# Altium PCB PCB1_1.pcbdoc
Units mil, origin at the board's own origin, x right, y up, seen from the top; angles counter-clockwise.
Board outline 2362.2 x 3149.61 mil, 4 copper layers (Top Layer, Inner1, Inner2, Bottom Layer), stack 62.447 mil thick; 35 components, 41 nets, 160 pads, 134 vias.
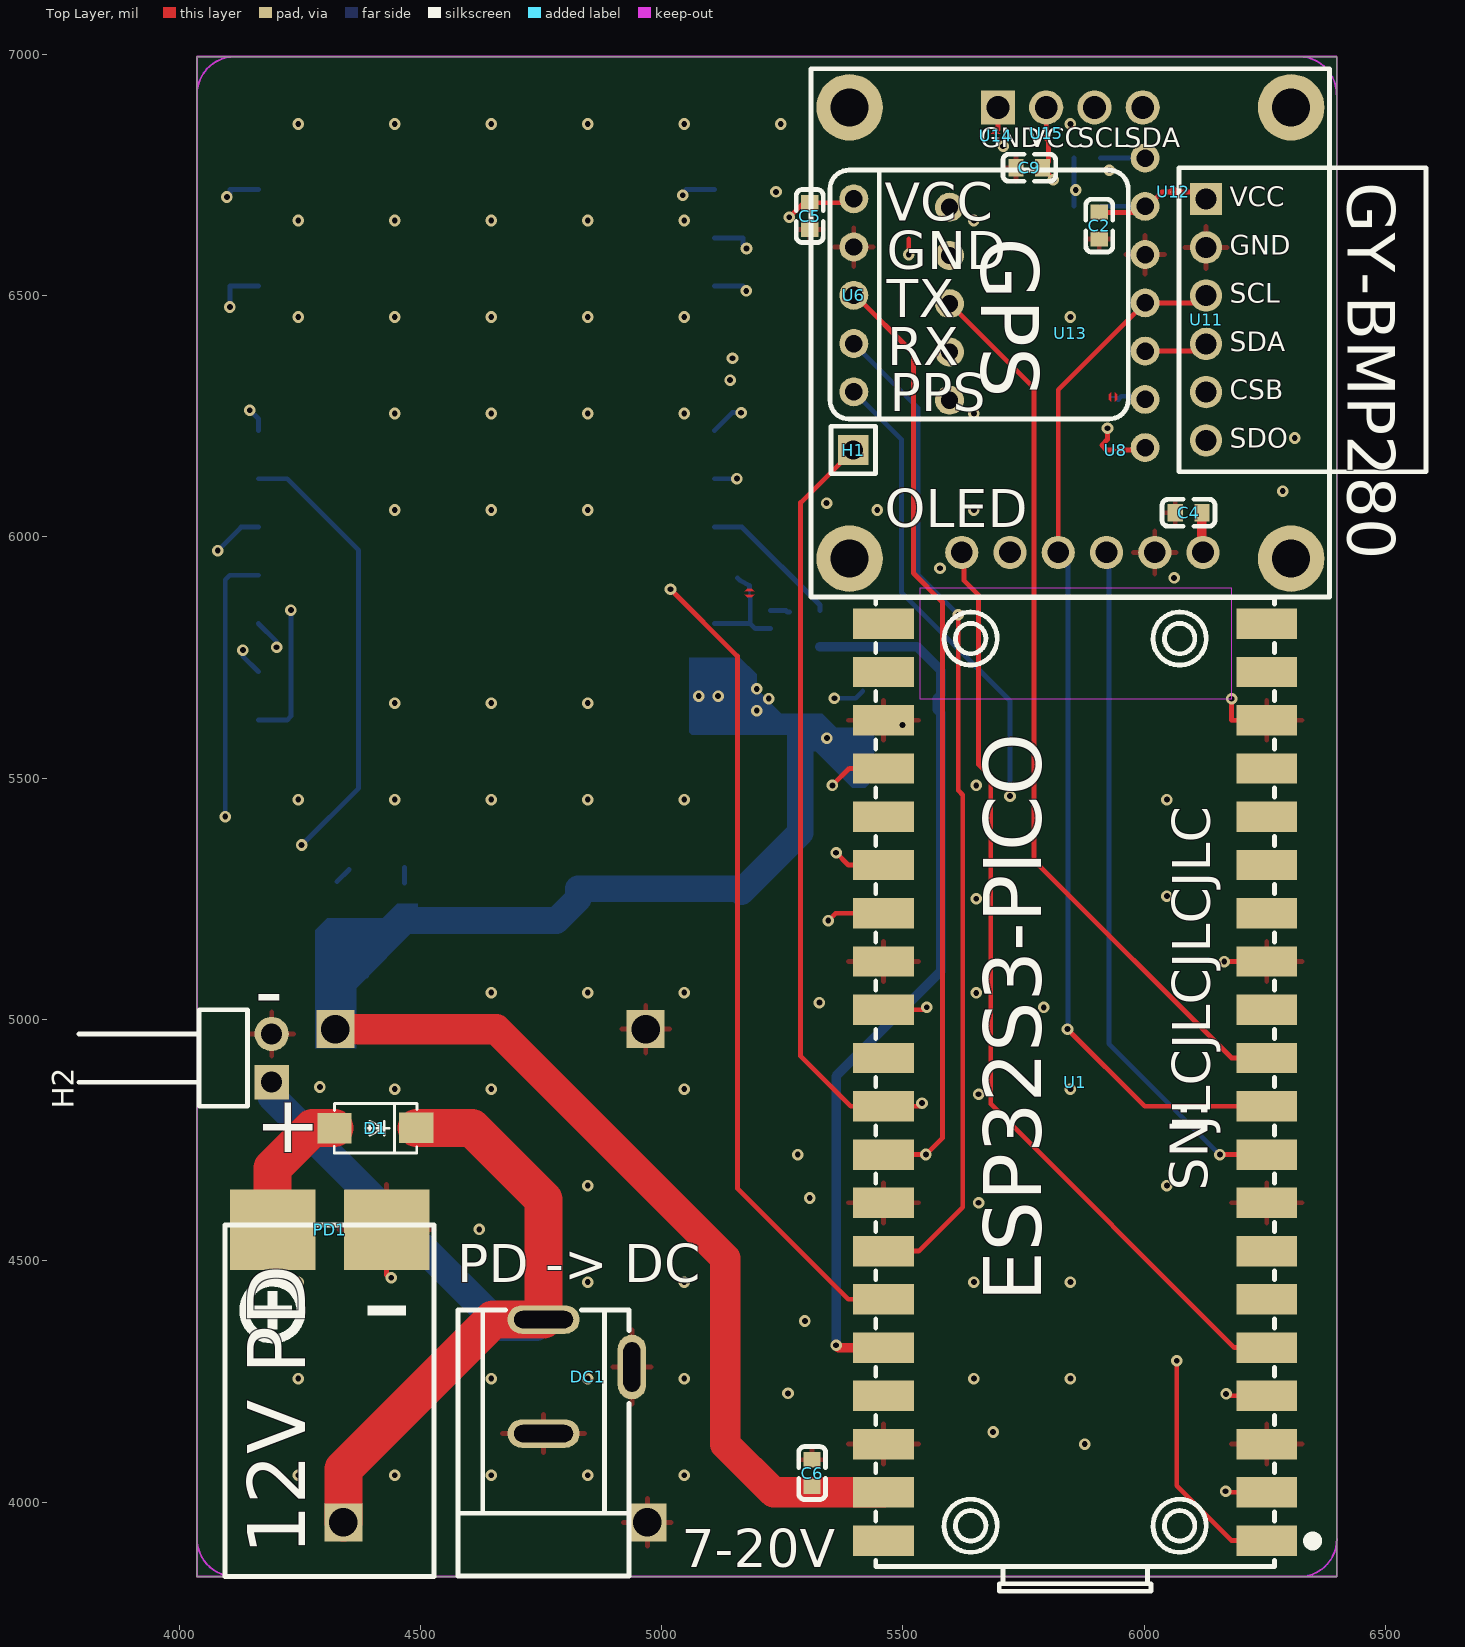
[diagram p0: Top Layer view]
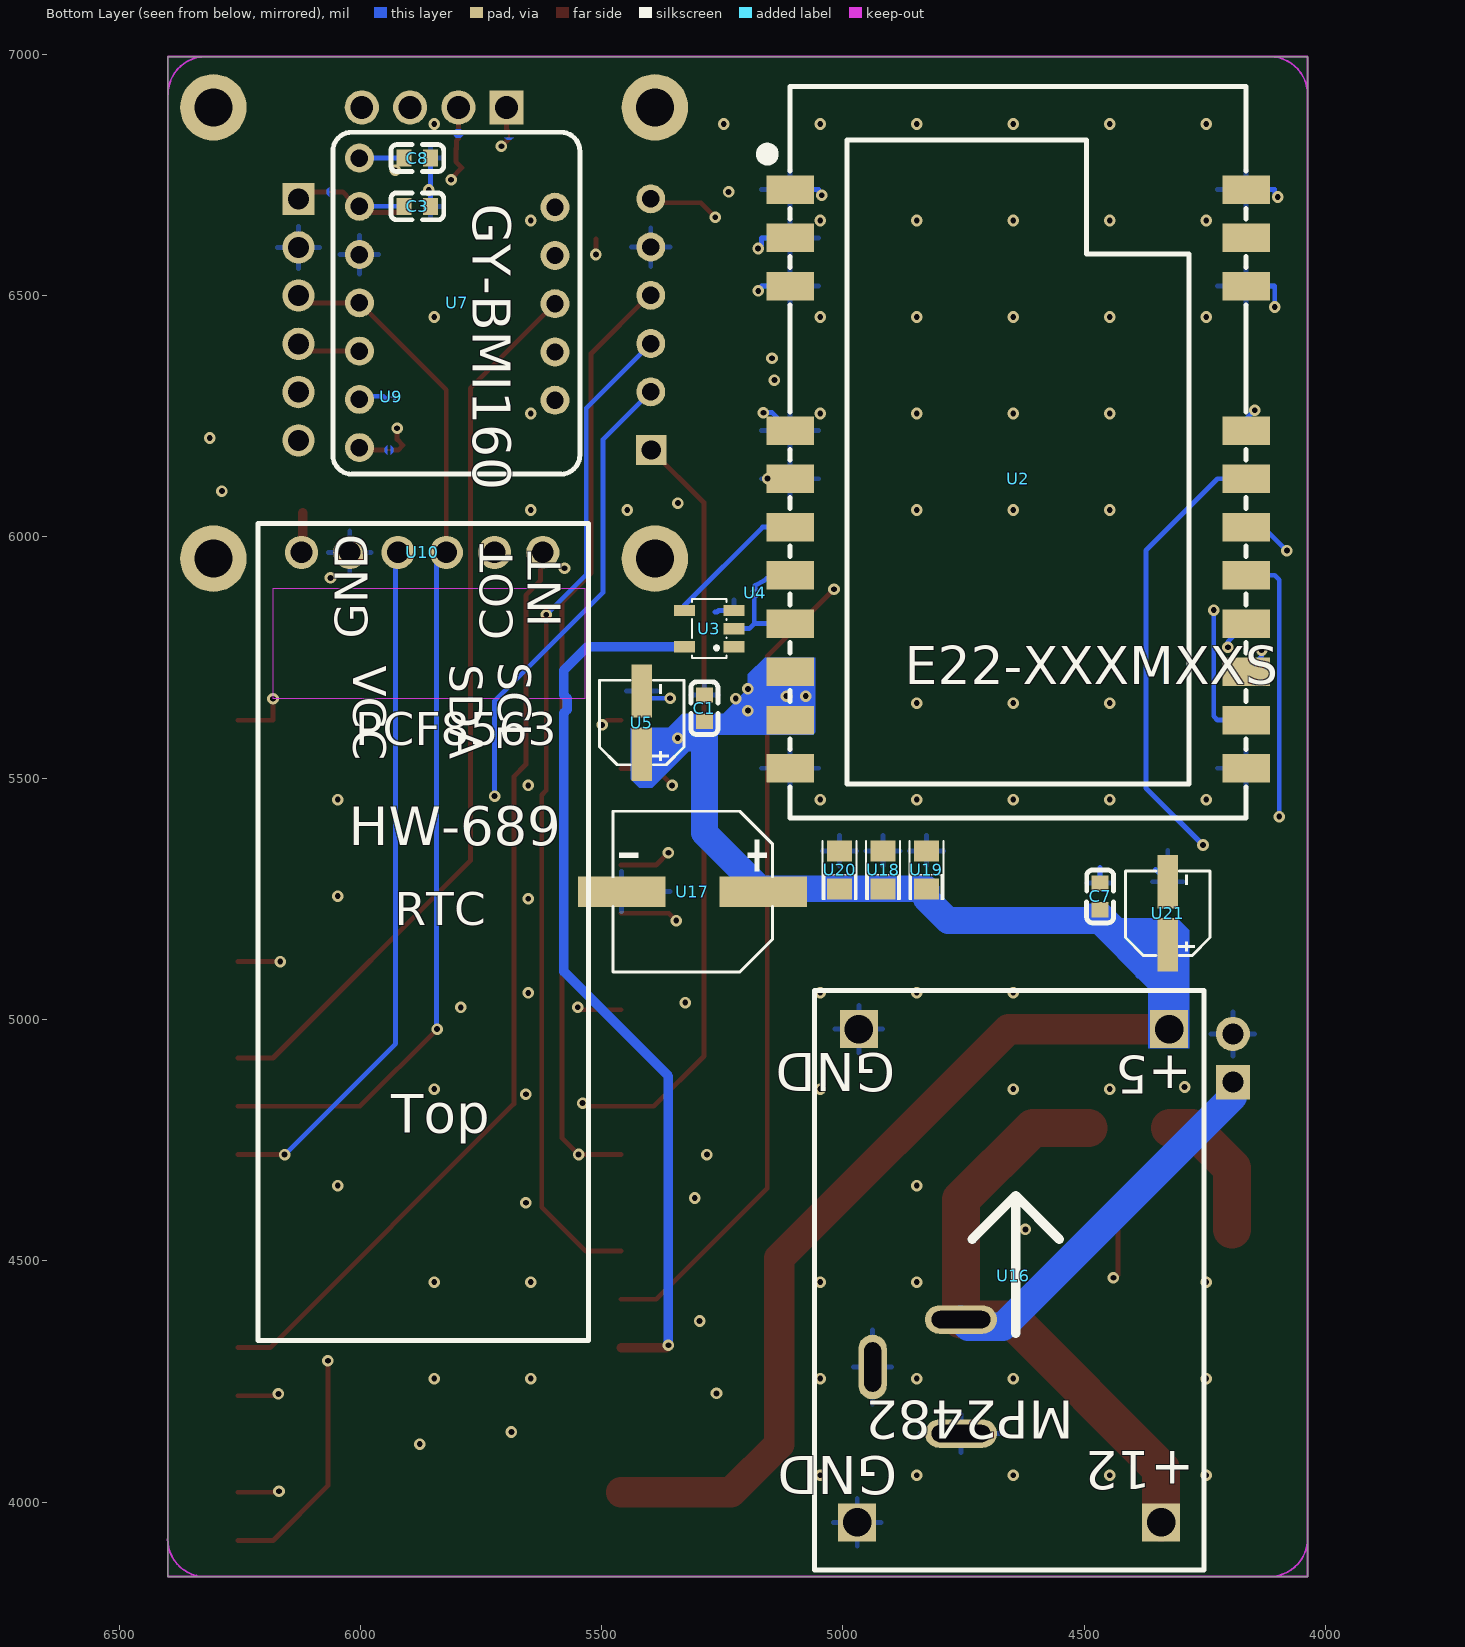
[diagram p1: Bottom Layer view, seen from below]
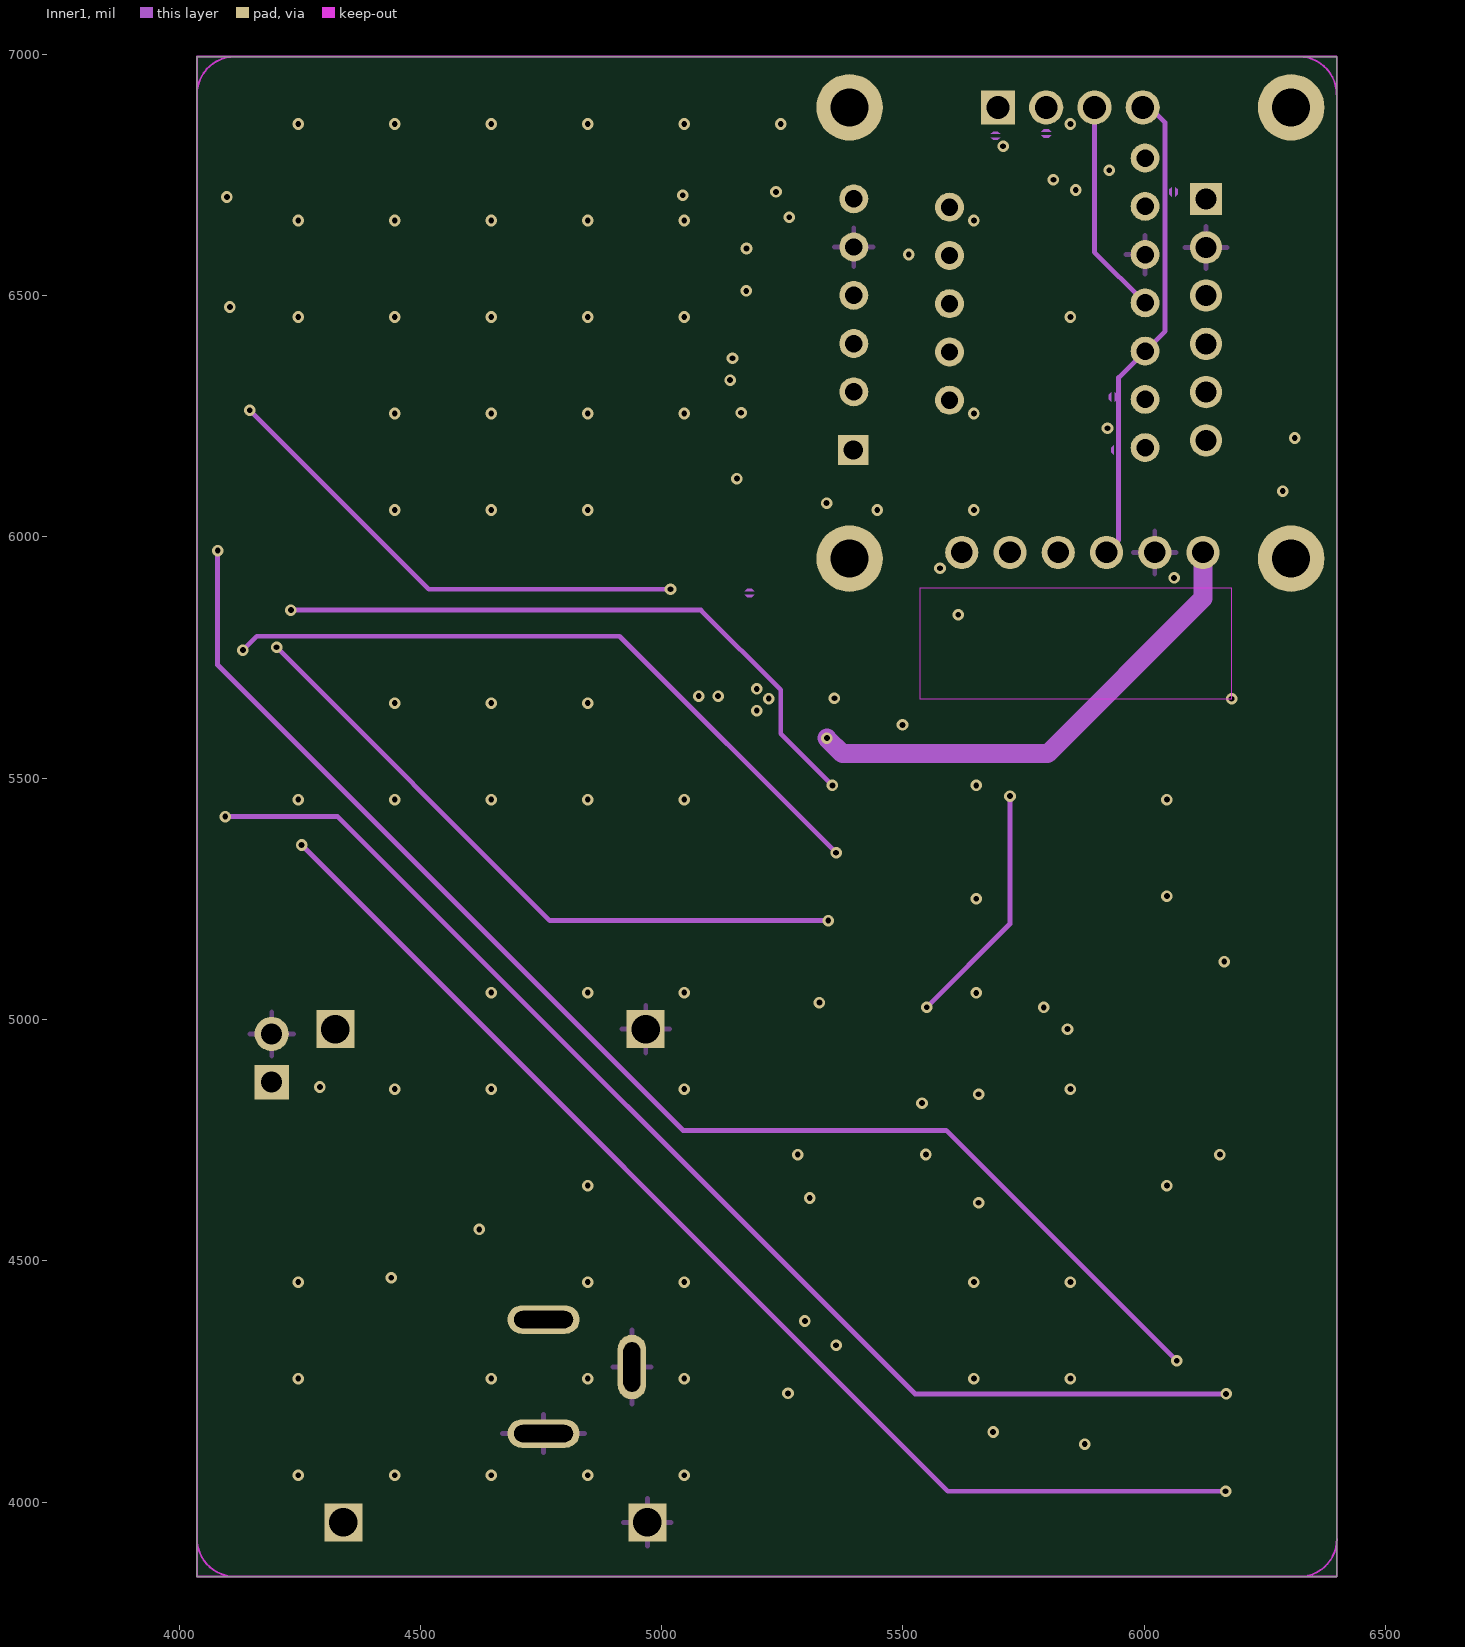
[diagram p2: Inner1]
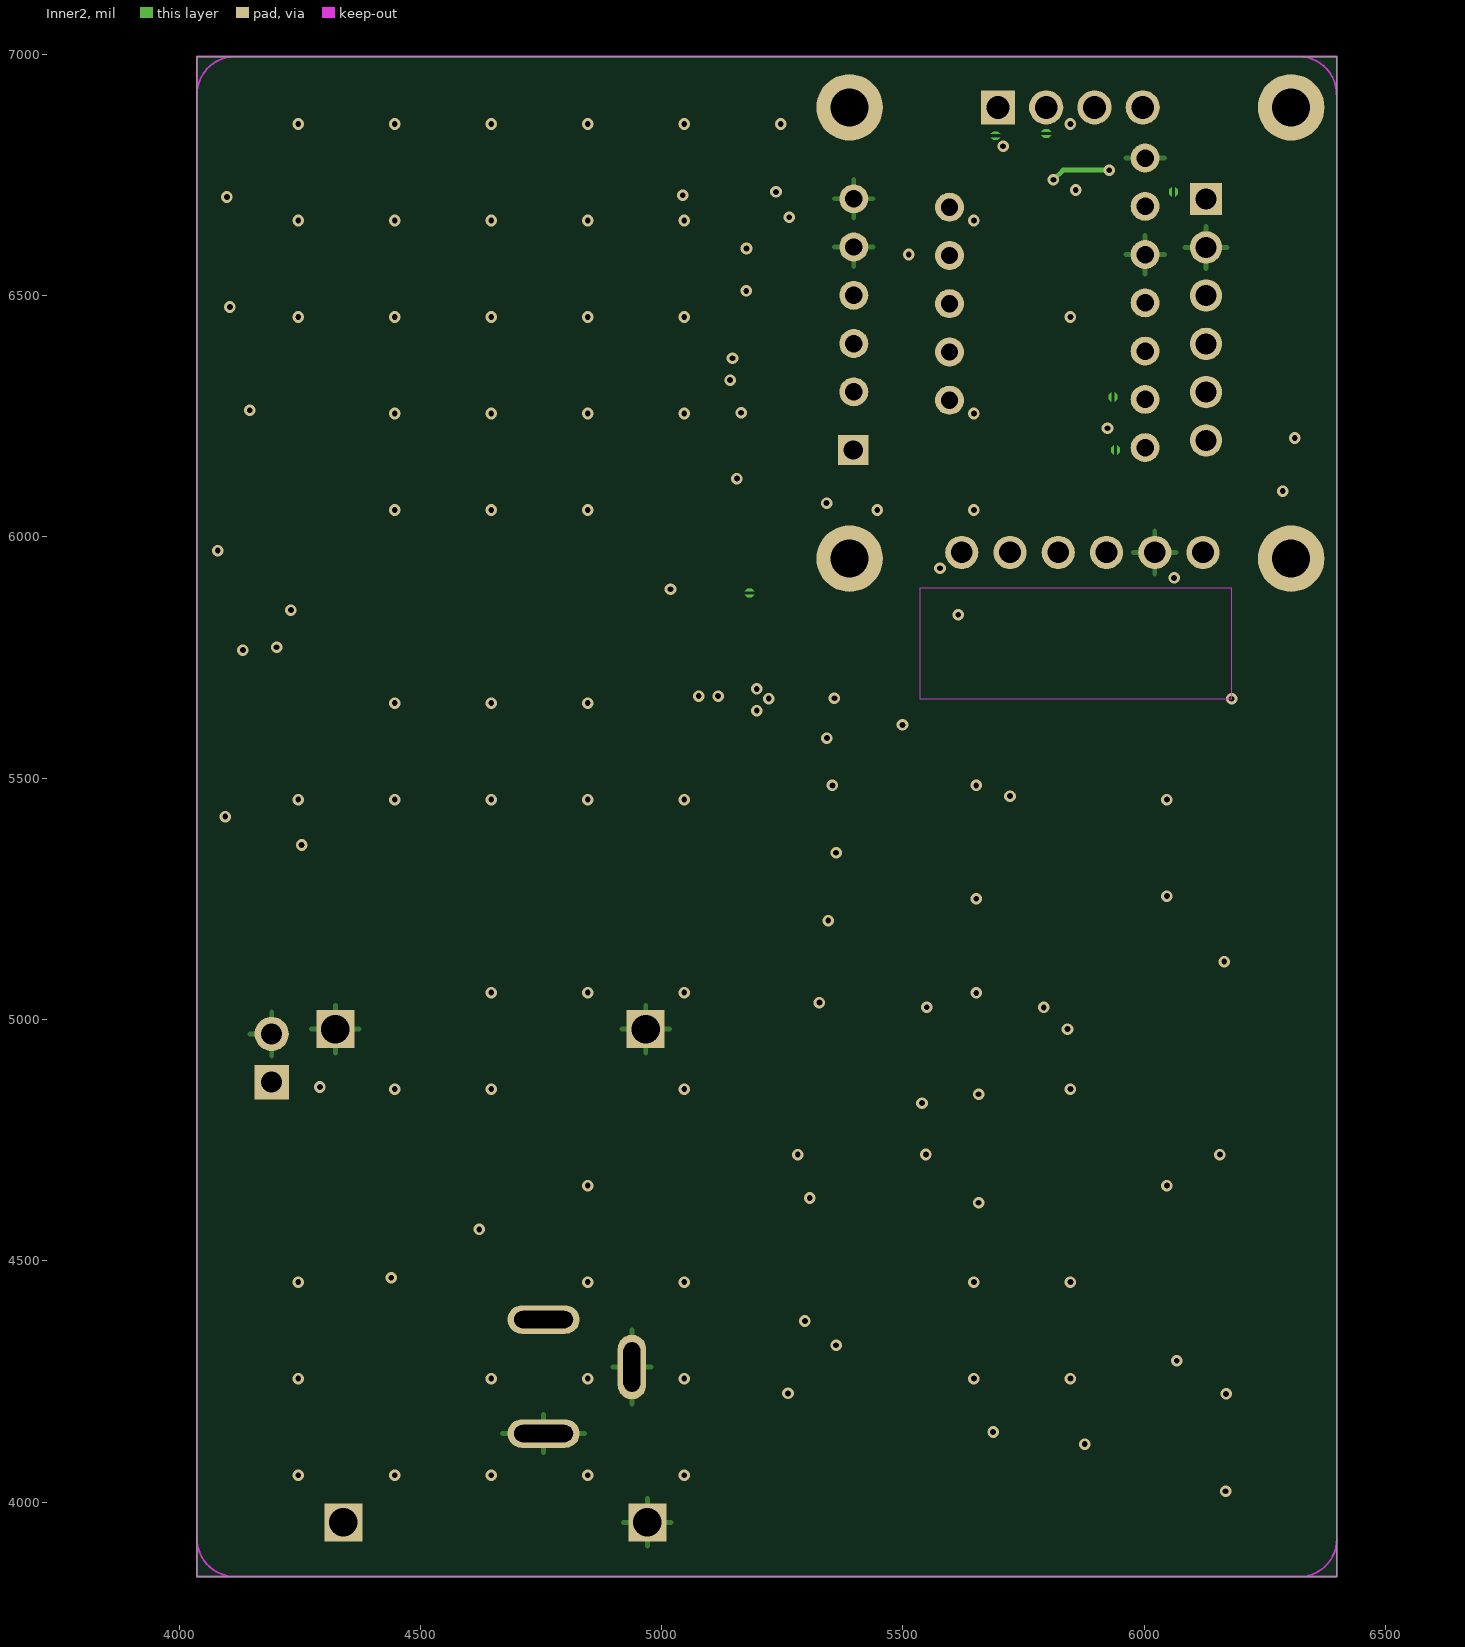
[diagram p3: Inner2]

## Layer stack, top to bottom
Top Layer: signal copper 1.378
Dielectric1: surface 8.283, 7628 RC49% 8.6mil, Dk 0
Inner1: signal copper 0.598
Dielectric2: surface 41.929, 1.1mm H/HOZ Copper, Dk 0
Inner2: signal copper 0.598
Dielectric3: surface 8.283, 7628 RC49% 8.6mil, Dk 0
Bottom Layer: signal copper 1.378

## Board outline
4036.85,6995.16 4036.85,3845.55 6399.06,3845.55 6399.06,6995.16

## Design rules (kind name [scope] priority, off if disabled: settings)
BoardOutlineClearance copperThickness1oz [All] p0: genericclearance=10 ignorepadtopadclearanceinfootprint=FALSE except(0: Arc-SplitContinuation Track-SplitContinuation SMDPad-SplitContinuation THPad-SplitContinuation Via-SplitContinuation Fill-SplitContinuation Poly-SplitContinuation Region-SplitContinuation Text-SplitContinuation)
BoardOutlineClearance copperThickness2oz [All] p0: genericclearance=10 ignorepadtopadclearanceinfootprint=FALSE except(0: Arc-SplitContinuation Track-SplitContinuation SMDPad-SplitContinuation THPad-SplitContinuation Via-SplitContinuation Fill-SplitContinuation Poly-SplitContinuation Region-SplitContinuation Text-SplitContinuation)
BoardOutlineClearance otherClearance [All] p0: genericclearance=10 ignorepadtopadclearanceinfootprint=FALSE except(0: Arc-SplitContinuation Track-SplitContinuation SMDPad-SplitContinuation THPad-SplitContinuation Via-SplitContinuation Fill-SplitContinuation Poly-SplitContinuation Region-SplitContinuation Text-SplitContinuation)
Clearance copperThickness1oz [All] p1: gap=7 ignorepadtopadclearanceinfootprint=FALSE
Clearance copperThickness2oz [All] p1: gap=7 ignorepadtopadclearanceinfootprint=FALSE
Clearance otherClearance [All] p1: gap=7 ignorepadtopadclearanceinfootprint=FALSE
DiffPairsRouting differentialPair [All] p1: maxuncoupledlength=10 minlimit=6 maxlimit=Infinity mostfreqgap=6 toplayer_minwidth=5 toplayer_prefwidth=10 toplayer_maxwidth=100 bottomlayer_minwidth=5 bottomlayer_prefwidth=10 bottomlayer_maxwidth=100 midlayer1_minwidth=5 midlayer1_prefwidth=10 midlayer1_maxwidth=100 midlayer2_minwidth=5 midlayer2_prefwidth=10 midlayer2_maxwidth=100
PasteMaskExpansion pasteMaskExpansion [All] p1: expansion=0
PlaneConnect innerPlane [All] p1: planeconnectstyle=Relief reliefexpansion=20 reliefentries=4 reliefconductorwidth=10 reliefairgap=10
PolygonConnect copperRegion [All] p1: connectstyle=Relief reliefentries=4 reliefconductorwidth=10 polygonreliefangle="90 Angle" airgapwidth=10
RoutingVias viaSize [All] p1: viastyle="Through Hole" holewidth=12.0078 minholewidth=11.811 maxholewidth=248.0314 width=12.0078 minwidth=11.811 maxwidth=248.0314
SolderMaskExpansion solderMaskExpansion [IsVia] p1: useseparateexpansions=TRUE expansion=-1000 expansionbottom=-1000
SolderMaskExpansion solderMaskExpansion [All] p2: useseparateexpansions=TRUE expansion=2 expansionbottom=2
Width copperThickness1oz [All] p1: maxlimit=100 minlimit=5 preferedwidth=10
Width copperThickness2oz [All] p1: maxlimit=100 minlimit=8 preferedwidth=10

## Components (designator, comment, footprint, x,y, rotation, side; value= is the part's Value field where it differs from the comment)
C1 "100nF" C0603 5286.85,5645 r270 bottom
C2 "100nF" C0603 5906.85,6645 r90 top
C3 "100nF" C0603 5881.85,6685 r0 bottom
C4 "100nF" C0603 6091.85,6050 r0 top
C5 "100nF" C0603 5306.85,6664.88 r90 top
C6 "100nF" C0603 5311.85,4060 r270 top
C7 "100nF" C0603 4466.85,5254.88 r270 bottom
C8 "100nF" C0603 5881.85,6785 r0 bottom
C9 "100nF" C0603 5761.85,6765 r0 top
D1 "SS54" SMA_L4.3-W2.6-LS5.0-FD 4406.85,4775 r0 top
DC1 "DC-005-A200" DC-IN-TH_DC-005-A200 4846.85,4260 r90 top
H1 "A254N01-0B1P51-H25A60" HDR-TH_1P-P2.54-V-M-3 5396.85,6180 r0 top
H2 "LAIL-PZ2.54-2P-W" HDR-TH_2P-P2.54-H-M-W10.0 4191.85,4920 r90 top
PD1 "" PDC004-PD诱骗模块 4311.85,4210 r180 top
U1 "ESP32-S3-Pico" LCC-40_L51.0-W21.0-P2.54-BL_RP2040-BASED 5856.85,4870 r90 top
U2 "E22-900M30S" WIRELM-SMD_E22-900M30S 4636.85,6120 r0 bottom
U3 "SN74LVC1G14DBVR" SOT-23-5_L3.0-W1.7-P0.95-LS2.8-BR 5276.85,5810 r180 bottom
U4 "" SB 5191.85,5880 r270 bottom
U5 "22uF" CAP-SMD_BD4.0-L4.3-W4.3-LS5.0-FD 5416.85,5615 r90 bottom
U6 "" ATGM336H 5651.85,6495 r270 top
U7 "" GY-BMI160 5716.85,6495 r180 bottom
U8 "" SB 5936.85,6190 r180 top
U9 "" SB 5931.85,6280 r180 bottom
U10 "PCF8563 HW-689 MODULE" PCF8563-I2C-2.54-1*6 5871.85,5175 r180 bottom
U11 "" GY-BMP280 6071.85,6765 r270 top
U12 "" SB 6056.85,6725 r180 top
U13 "" "OLED 0.96寸" 5696.85,6890 r0 top
U14 "" SB 5701.85,6835 r90 top
U15 "" SB 5806.85,6840 r90 top
U16 "" MP2482 4251.85,5060 r0 bottom
U17 "16V470UF" CAP-SMD_BD8.0-L8.3-W8.3-LS9.3-FD 5311.85,5265 r0 bottom
U18 "10uf" CAP-SMD_L2.0-W1.3-FD 4916.85,5310 r90 bottom
U19 "10uf" CAP-SMD_L2.0-W1.3-FD 4826.85,5310 r90 bottom
U20 "10uf" CAP-SMD_L2.0-W1.3-FD 5006.85,5310 r90 bottom
U21 "22uF" CAP-SMD_BD4.0-L4.3-W4.3-LS5.0-FD 4326.85,5220 r90 bottom

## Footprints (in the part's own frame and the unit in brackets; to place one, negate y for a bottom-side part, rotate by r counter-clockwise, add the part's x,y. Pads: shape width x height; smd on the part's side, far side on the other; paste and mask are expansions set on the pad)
ATGM336H [mil]
  round 60 hole 36: 1(-205.63,-253.74) 2(-105.63,-253.74) 3(-5.63,-253.74) 4(94.37,-253.74) 5(194.37,-253.74)
  silkscreen extent -265,-303 251,315
C0603 [mm]
  rect 0.8x0.9 smd: 1(-0.7,0) 2(0.7,0)
  silkscreen extent -1.39,-0.71 1.39,0.71
CAP-SMD_BD4.0-L4.3-W4.3-LS5.0-FD [mm]
  rect 2.8x1.1 smd: 1(-1.661,0) 2(1.661,0)
  silkscreen extent -2.22,-2.23 2.24,2.23
CAP-SMD_BD8.0-L8.3-W8.3-LS9.3-FD [mm]
  rect 4.6x1.6 smd: 1(-3.724,0) 2(3.724,0)
  silkscreen extent -4.23,-4.23 4.18,4.23
CAP-SMD_L2.0-W1.3-FD [mm]
  rect 1.1x1.3 smd paste+0 mask+0.05: 1(-1,0) 2(1,0)
  silkscreen extent -1.57,-0.89 1.52,0.89
DC-IN-TH_DC-005-A200 [mm]
  oval 1.5x3.8 hole 0.9 slot 3.1 at 90 deg copper offset -0.001,0: 1(3.001,2.325)
  oval 1.5x3.8 hole 0.9 slot 3.1 at 90 deg copper offset 0,0: 2(-3,2.325)
  oval 3.4x1.5 hole 0.9 slot 2.6 at 0 deg copper offset 0,-0.001: 3(0.5,-2.325)
  silkscreen extent -10.5,-2.17 3.5,6.83
GY-BMI160 [mil]
  round 60 hole 36: 1(-285,290) 2(-285,190) 3(-285,90) 4(-285,-10) 5(-285,-110) 6(-285,-210) 7(-285,-310) 8(120.25,-211.79) 9(120.25,-111.79) 10(120.25,-11.79) 11(120.25,88.21) 12(120.25,188.21)
  silkscreen extent -340,-365 172,344
GY-BMP280 [mm]
  rect 1.7x1.7 hole 1.1: 1(1.65,1.43)
  round 1.7 hole 1.1: 2(4.19,1.43) 3(6.73,1.43) 4(9.27,1.43) 5(11.81,1.43) 6(14.35,1.43)
  silkscreen extent 0,0 16,13
HDR-TH_1P-P2.54-V-M-3 [mm]
  rect 1.6x1.6 hole 1.02: 1(0,0)
  silkscreen extent -1.17,-1.25 1.17,1.25
HDR-TH_2P-P2.54-H-M-W10.0 [mm]
  rect 1.8x1.8 hole 1.1: 1(-1.27,0)
  round 1.8 hole 1.1: 2(1.27,0)
  silkscreen extent -2.54,1.27 2.54,10.16
LCC-40_L51.0-W21.0-P2.54-BL_RP2040-BASED [mm]
  rect 1.6x3.2 smd: 1(-24.13,-10.087) 2(-21.59,-10.087) 3(-19.05,-10.087) 4(-16.51,-10.087) 5(-13.97,-10.087) 6(-11.43,-10.087) 7(-8.89,-10.087) 8(-6.35,-10.087) 9(-3.81,-10.087) 10(-1.27,-10.087) 11(1.27,-10.087) 12(3.81,-10.087) 13(6.35,-10.087) 14(8.89,-10.087) 15(11.43,-10.087) 16(13.97,-10.087) 17(16.51,-10.087) 18(19.05,-10.087) 19(21.59,-10.087) 20(24.13,-10.087) 21(24.13,10.087) 22(21.59,10.087) 23(19.05,10.087) 24(16.51,10.087) 25(13.97,10.087) 26(11.43,10.087) 27(8.89,10.087) 28(6.35,10.087) 29(3.81,10.087) 30(1.27,10.087) 31(-1.27,10.087) 32(-3.81,10.087) 33(-6.35,10.087) 34(-8.89,10.087) 35(-11.43,10.087) 36(-13.97,10.087) 37(-16.51,10.087) 38(-19.05,10.087) 39(-21.59,10.087) 40(-24.13,10.087)
  silkscreen extent -26.8,-12.75 25.5,10.5
MP2482 [mm]
  rect 2x2 hole 1.5: 1(2.25,28) 2(18.25,28) 3(18.161,2.032) 4(1.828,2.032)
  silkscreen extent 0,0 20.5,30.5
"OLED 0.96寸" [mm]
  rect 1.8x1.8 hole 1.2 paste+0 mask+0.102: 1(0,0)
  round 1.8 hole 1.2 paste+0 mask+0.102: 2(2.54,0) 3(5.08,0) 4(7.62,0)
  round 3.5 hole 2 paste+0 mask+0.102: 5(-7.808,0) 6(15.433,0) 7(15.433,-23.749) 8(-7.808,-23.749)
  silkscreen extent -9.84,-25.77 17.46,2.03
PCF8563-I2C-2.54-1*6 [mm]
  round 1.75 hole 1.14 paste+0 mask+0.102: 1(-6.35,20.14) 2(-3.81,20.14) 3(-1.27,20.14) 4(1.27,20.14) 5(3.81,20.14) 6(6.35,20.14)
  silkscreen extent -8.64,-21.34 8.76,21.66
PDC004-PD诱骗模块 [mm]
  rect 4.5x4.25 smd: 1(-3,-9) 2(3,-9)
  silkscreen extent -5.5,-9.25 5.5,9.25
SB [mil]
  round 2.22 smd: 1(2.22,10) 2(-9.72,10)
  Top Layer region: 0,0 0,20 5,15 5,5
  Top Layer region: -7.5,20 -7.5,0 -12.5,5 -12.5,15
  Top Layer lines w3.94: 2.5,10 -10,10 2.5,10
  Bottom Layer region: 0,0 0,20 5,15 5,5
  Bottom Layer region: -7.5,20 -7.5,0 -12.5,5 -12.5,15
  Multi-Layer region: 0,0 0,20 5,15 5,5
  Multi-Layer region: -7.5,20 -7.5,0 -12.5,5 -12.5,15
SMA_L4.3-W2.6-LS5.0-FD [mm]
  rect 1.8x1.62 smd: 1(-2.15,-0.009) 2(2.15,0.009)
  silkscreen extent -2.17,-1.32 2.19,1.29
SOT-23-5_L3.0-W1.7-P0.95-LS2.8-BR [mm]
  rect 1.1x0.6 smd: 1(1.3,-0.95) 2(1.3,0) 3(1.3,0.95) 4(-1.3,0.95) 5(-1.3,-0.95)
  silkscreen extent -0.9,-1.55 0.9,1.55
WIRELM-SMD_E22-900M30S [mm]
  rect 2.5x1.5 smd: 1(12,-15.23) 2(12,-12.69) 3(12,-10.15) 4(12,-2.55) 5(12,-0.01) 6(12,2.53) 7(12,5.07) 8(12,7.61) 9(12,10.15) 10(12,12.69) 11(12,15.23) 12(-12,15.23) 13(-12,12.69) 14(-12,10.15) 15(-12,7.61) 16(-12,5.07) 17(-12,2.53) 18(-12,-0.01) 19(-12,-2.55) 20(-12,-10.15) 21(-12,-12.69) 22(-12,-15.23)
  silkscreen extent -12,-20.66 13.5,17.84

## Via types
v1: diameter 24.02, hole 12, Top Layer to Bottom Layer, 95 vias
v2: diameter 24, hole 12, Top Layer to Bottom Layer, 39 vias

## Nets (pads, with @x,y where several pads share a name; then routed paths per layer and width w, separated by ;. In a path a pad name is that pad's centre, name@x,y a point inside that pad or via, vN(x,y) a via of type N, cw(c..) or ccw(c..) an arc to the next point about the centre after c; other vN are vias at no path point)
$1N26: D1.1 PD1.2 | length 290.3
  Top Layer w78.74: PD1.2 4193.74,4691.89 4276.48,4774.63 D1.1
$1N115: U7.7 U8.2 | length 33.3
  Top Layer w10: U8.2@5946.85,6180 U7.7@5980.18,6180
$1N117: U7.6 U9.2 | length 62.3
  Bottom Layer w10: 5946.85,6285.05 5945.85,6285.05 5952.25,6291.45 5995.42,6291.45 U7.6@6001.85,6285.05
$1N126: U11.1 U12.2 | length 67.5
  Top Layer w10: U12.2@6066.85,6715 6079.82,6715 6113.19,6715 U11.1
$1N132: U13.1 U14.1 | length 69.6
  Top Layer w10: U14.1@5691.85,6837.55 5691.85,6838.55 5696.85,6843.55 U13.1@5696.85,6905.05
$1N133: U13.2 U15.1 | length 16.2
  Top Layer w10: U15.1@5796.85,6842.5 U13.2@5796.85,6858.66
+5V: C1.2 C4.2 C5.2 C6.2 C7.2 C8.2 C9.2 U1.39 U2.9 U2.10 U5.1 U6.1 U7.1 U10.1 U15.2 U16.4 U17.1 U18.1 U19.1 U20.1 U21.1 | length 5521.2
  Top Layer w10: v1(5264.35,6662.45) 5294.34,6692.44 C5.2 5389.92,6692.44 U6.1 ; 5796.85,6825 5800.94,6820.91 5800.94,6803.56 ; 5801.85,6805 5801.85,6777.44 C9.2 5811.85,6742.56 v1(5811.85,6740)
  Top Layer w19.68: C4.2 6119.41,5970.35 U10.1
  Top Layer w62.99: U16.4 4656.85,4980 5131.85,4505 5131.85,4120 5231.85,4020 5332.47,4020 U1.39
  Inner1 w39.37: v2(5342.33,5583.06) 5374.74,5550.65 5799.85,5550.65 6121.85,5872.65 U10.1
  Inner2 w10: v1(5811.85,6740) 5831.85,6760 v1(5927.48,6760)
  Bottom Layer w10: U16.4@4323.85,4980.05 4323.85,5119.05 U21.1@4326.85,5122.05 ; U21.1@4326.85,5154.65 U21.1@4326.85,5122.05 ; C7.2@4466.85,5227.35 4466.85,5201.55 4388.35,5123.05 4388.35,5090.05 4327.35,5090.05 4326.85,5089.45 U21.1@4326.85,5122.05 ; 4494.55,5227.35 4516.95,5205.05 ; U2.10 U2.10@5138.95,5620.35 ; U2.9 5168.55,5720.35 5168.55,5650.05 U2.10@5138.95,5620.35 ; U17.1@5159.57,5270.63 5160.62,5269.6 U17.1@5165.25,5265.05 ; 5286.85,5559.85 U5.1@5416.85,5559.85 ; 5286.85,5590.05 5286.85,5617.45 5259.15,5617.45 5256.65,5615.05 5173.95,5615.05 5168.55,5620.35 U2.10@5138.95,5620.35 ; v2(5342.33,5583.06) 5393.64,5583.06 U5.1@5416.85,5559.85 ; U5.1@5416.85,5549.65 U5.1@5416.85,5559.85 ; C8.2@5909.45,6785.05 U7.1@6001.85,6785.05
  Bottom Layer w55.12: 4476.85,5205 4516.95,5205 4781.85,5205 4826.85,5250 U19.1 U18.1 U20.1 U17.1@5159.57,5270.63 ; U17.1@5159.59,5270.63 5160.62,5269.6 U17.1 5286.85,5386.63 5286.85,5559.85 5286.85,5590
  other v1: 5196.85,5640 5221.85,5665 5076.85,5670 5116.85,5670 5196.85,5685
BMI_3V: C2.2 C3.2 U7.2 U12.1 | length 231.3
  Top Layer w10: C2.2 5989.41,6672.56 U7.2 ; U7.2@6021.85,6700 6036.85,6715 U12.1@6054.35,6715
  Bottom Layer w10: C3.2@5909.45,6685.05 U7.2@6001.85,6685.05
ESP_3V3: U1.36 U3.5 | length 1864.9
  Top Layer w19.68: v2(5361.45,4324.95) 5366.35,4320.05 U1.36@5459.75,4320.05
  Bottom Layer w19.68: U3.5@5328.05,5772.65 5529.23,5772.65 5578.05,5723.79 5578.05,5672.2 5571.12,5665.28 5571.12,5642.23 5578.05,5635.3 5578.05,5099.25 5361.45,4882.65 v2(5361.45,4324.95)
GND: C1.1 C2.1 C3.1 C4.1 C5.1 C6.1 C7.1 C8.1 C9.1 DC1.2 DC1.3 H2.2 PD1.1 U1.3 U1.8 U1.13 U1.18 U1.23 U1.28 U1.33 U1.38 U2.1 U2.2 U2.3 U2.4 U2.5 U2.11 U2.12 U2.20 U2.22 U3.3 U5.2 U6.2 U7.3 U8.1 U10.2 U11.2 U14.2 U16.2 U16.3 U17.2 U18.2 U19.2 U20.2 U21.2 | length 1280.5
  Top Layer w10: PD1.1@4429.95,4564.35 4429.95,4470.65 4433.35,4470.65 v2(4439.45,4464.55) ; U1.23@5459.75,5620.05 5489.35,5620.05 v2(5499.05,5610.35) ; v2(5511.85,6585.15) 5511.85,6617.45 ; U14.2@5691.85,6825.05 v2(5707.55,6809.35) ; v2(5923.87,6225) 5923.87,6202.02 5911.85,6190 5921.85,6180 U8.1@5934.35,6180 ; v2(6165.95,5119.85) 6253.75,5119.85 U1.13@6253.95,5120.05 ; v2(6180.95,5664.65) 6180.95,5620.05 U1.18@6253.95,5620.05
  Bottom Layer w10: v2(4098.95,6704.35) 4105.15,6710.65 4105.15,6719.65 U2.22@4164.45,6719.65 ; v2(4105.15,6476.45) 4105.15,6519.65 U2.20@4164.45,6519.65 ; U21.2 4352.05,5310.55 4352.55,5310.55 ; C7.1@4466.85,5282.45 4466.85,5314.95 ; v2(5043.85,6707.95) 5050.05,6714.15 5050.05,6719.65 U2.1@5109.25,6719.65 ; U2.5 5153.35,6120.35 5153.75,6120.75 v2(5155.95,6120.75) ; U2.4 5146.35,6257.45 v2(5164.65,6257.45) ; U2.3@5109.25,6519.65 5168.55,6519.65 5168.55,6516.45 v2(5175.25,6509.65) ; U2.2@5109.25,6619.65 5168.55,6619.65 5168.55,6604.85 v2(5175.75,6597.55) ; U3.3@5225.65,5847.45 5257.35,5847.45 5260.65,5844.05 5264.85,5844.05 ; v2(5358.05,5665.55) 5402.05,5665.55 U5.2 ; C3.1@5854.25,6685.05 5854.25,6714.85 v2(5858.25,6718.85) 5854.25,6722.85 C8.1@5854.25,6785.05
  other v1: 4246.95,4055.65 4446.95,4055.65 4646.95,4055.65 4846.95,4055.65 5046.95,4055.65 5876.85,4120 5686.85,4145 5261.85,4225 4246.95,4255.65 4646.95,4255.65 4846.95,4255.65 5046.95,4255.65 5646.95,4255.65 5846.95,4255.65 5296.85,4375 4246.95,4455.65 4846.95,4455.65 5046.95,4455.65 5646.95,4455.65 5846.95,4455.65 4621.85,4565 5656.85,4620 5306.85,4630 4846.95,4655.65 6046.95,4655.65 5281.85,4720 5656.85,4845 4446.95,4855.65 4646.95,4855.65 5046.95,4855.65 5846.95,4855.65 4291.85,4860 5791.85,5025 5326.85,5035 5651.85,5055 4646.95,5055.65 4846.95,5055.65 5046.95,5055.65 5651.85,5250 6046.95,5255.65 4246.95,5455.65 4446.95,5455.65 4646.95,5455.65 4846.95,5455.65 5046.95,5455.65 6046.95,5455.65 5651.85,5485 4446.95,5655.65 4646.95,5655.65 4846.95,5655.65 5576.85,5935 4446.95,6055.65 4646.95,6055.65 4846.95,6055.65 5446.95,6055.65 5646.95,6055.65 5341.85,6070 6286.85,6095 6311.85,6205 4446.95,6255.65 4646.95,6255.65 4846.95,6255.65 5046.95,6255.65 5646.95,6255.65 5141.85,6325 5146.85,6370 4246.95,6455.65 4446.95,6455.65 4646.95,6455.65 4846.95,6455.65 5046.95,6455.65 5846.95,6455.65 4246.95,6655.65 4446.95,6655.65 4646.95,6655.65 4846.95,6655.65 5046.95,6655.65 5646.95,6655.65 5236.85,6715 4246.95,6855.65 4446.95,6855.65 4646.95,6855.65 4846.95,6855.65 5046.95,6855.65 5246.95,6855.65 5846.95,6855.65
  other v2: 6061.85,5915
GPIO1: U1.24 U2.13 | length 1737
  Top Layer w10: v2(5353.85,5485.01) 5388.89,5520.05 U1.24@5459.75,5520.05
  Inner1 w10: v2(4231.61,5848.37) 5081.43,5848.37 5246.85,5682.95 5246.85,5592.01 v2(5353.85,5485.01)
  Bottom Layer w10: U2.13@4164.45,5620.35 4223.65,5620.35 4231.61,5628.31 v2(4231.61,5848.37)
GPIO2: U1.25
GPIO4: U1.26 U2.14 | length 1594.2
  Top Layer w10: v2(5361.45,5345.35) 5361.45,5345.25 5386.65,5320.05 U1.26@5459.75,5320.05
  Inner1 w10: v2(4132.25,5765.35) 4161.05,5794.15 4912.65,5794.15 v2(5361.45,5345.35)
  Bottom Layer w10: v2(4132.25,5765.35) 4132.25,5752.55 U2.14@4164.45,5720.35
GPIO5: U1.27 U2.15 | length 1563.2
  Top Layer w10: v2(5345.35,5204.95) 5360.45,5220.05 U1.27@5459.75,5220.05
  Inner1 w10: v2(4202.05,5771.17) 4768.27,5204.95 v2(5345.35,5204.95)
  Bottom Layer w10: U2.15@4164.45,5820.35 4202.05,5782.75 v2(4202.05,5771.17)
GPIO6: U1.29 U6.5 | length 1572.6
  Top Layer w10: U1.29@5459.75,5020.05 5543.95,5020.05 v2(5549.25,5025.35)
  Inner1 w10: v2(5549.25,5025.35) 5721.85,5197.95 v2(5721.85,5462.95)
  Bottom Layer w10: U6.5 5496.85,6201.89 5496.85,5885 5721.85,5660 v2(5721.85,5462.95)
GPIO7: H1.1 U1.31 | length 1598.6
  Top Layer w10: H1.1 5287.83,6070.98 5287.83,4924.02 5391.85,4820 U1.31 ; U1.31@5459.75,4820.05 5532.75,4820.05 v2(5539.45,4826.75)
GPIO8: U1.32 U6.3 | length 1960.6
  Top Layer w10: U6.3 5401.22,6500.63 5521.85,6380 5521.85,5925 5581.85,5865 5581.85,4754.25 v2(5547.65,4720.05) U1.32@5459.75,4720.05
GPIO9: U1.34 U6.4 | length 2084.9
  Top Layer w10: U1.34@5459.75,4520.05 5532.75,4520.05 5623.96,4611.26 5623.96,5465.17 5614.56,5474.57 v2(5614.56,5838.75)
  Bottom Layer w10: U6.4 5531.85,6266.89 5531.85,5921.46 v2(5614.56,5838.75)
GPIO10: U1.35 U2.19 | length 2772.2
  Top Layer w10: v2(5018.35,5891.55) 5156.85,5753.05 5156.85,4649.85 5386.65,4420.05 U1.35@5459.75,4420.05
  Inner1 w10: v2(4146.45,6262.45) 4517.35,5891.55 v2(5018.35,5891.55)
  Bottom Layer w10: v2(4146.45,6262.45) 4164.45,6244.45 U2.19@4164.45,6220.35
GPIO11: U1.1 U2.17 | length 3419.2
  Top Layer w10: v2(6067.25,4292.55) 6067.25,4033.75 6180.95,3920.05 U1.1@6253.95,3920.05
  Inner1 w10: v2(4079.85,5971.65) 4079.85,5734.5 5044.25,4770 5589.8,4770 v2(6067.25,4292.55)
  Bottom Layer w10: v2(4079.85,5971.65) 4128.55,6020.35 U2.17@4164.45,6020.35
GPIO12: U1.2 U2.18 | length 3484.2
  Top Layer w10: v2(6168.55,4022.35) 6170.85,4020.05 U1.2@6253.95,4020.05
  Inner1 w10: v2(4253.75,5361.45) 5592.85,4022.35 v2(6168.55,4022.35)
  Bottom Layer w10: U2.18@4164.45,6120.35 4223.65,6120.35 4371.85,5972.15 4371.85,5479.55 v2(4253.75,5361.45)
GPIO13: U1.4 U2.16 | length 3218.9
  Top Layer w10: v2(6169.65,4224.05) 6173.65,4220.05 U1.4@6253.95,4220.05
  Inner1 w10: v2(4095.55,5420.35) 4328.65,5420.35 5524.95,4224.05 v2(6169.65,4224.05)
  Bottom Layer w10: v2(4095.55,5420.35) 4095.55,5910.75 4105.15,5920.35 U2.16@4164.45,5920.35
GPIO14: U1.5 U10.6 | length 1949
  Top Layer w10: U10.6 5626.85,5962.91 5626.85,5908.96 5656.85,5878.96 5656.85,5528.27 5681.85,5503.27 5681.85,4825 6186.8,4320.05 U1.5@6253.95,4320.05
GPIO15: U1.6
GPIO16: U1.7
GPIO17: U1.9 U7.5 U10.3 U11.4 U13.4 | length 2581.5
  Top Layer w10: U7.5 6113.11,6385 U11.4 ; v1(6156.85,4720) U1.9
  Inner1 w10: U10.3 5946.85,5992.91 5946.85,6330.05 6001.85,6385.05 6043.15,6426.35 6043.15,6858.65 U13.4@5996.85,6905.05
  Bottom Layer w10: U10.3 5926.85,5962.91 5926.85,4950 v1(6156.85,4720)
GPIO18: U1.10 U7.4 U10.4 U11.3 U13.3 | length 2663.5
  Top Layer w10: U10.4 5821.85,6305.05 U7.4@6001.82,6485.03 ; v2(5840.95,4980.05) 6000.95,4820.05 U1.10@6253.95,4820.05 ; U7.4 6113.11,6485 U11.3
  Inner1 w10: U13.3@5896.85,6905.05 5896.85,6590.05 U7.4@6001.85,6485.05
  Bottom Layer w10: U10.4 5841.85,5947.91 5841.85,4980.95 v2(5840.95,4980.05)
GPIO33: U1.11 U7.10 | length 1878.2
  Top Layer w10: U7.10@5596.65,6483.25 5771.85,6307.98 5771.85,5329.15 6180.95,4920.05 U1.11@6253.95,4920.05
GPIO34: U1.12
GPIO35: U1.14
GPIO36: U1.15
GPIO37: U1.16
GPIO38: U1.17
GPIO39: U1.19
GPIO40: U1.20
GPIO41: U1.22
GPIO42: U1.21
RADIO_DIO2: U2.8 U3.2 U4.1 | length 178.6
  Bottom Layer w10: U2.8 5183.65,5820.35 ; U4.1@5181.85,5877.5 5183.65,5875.7 5183.65,5864.53 5183.65,5820.35 ; U3.2@5225.65,5810.05 5193.95,5810.05 5183.65,5820.35
RADIO_RXEN: U2.6 U3.4 | length 297.1
  Bottom Layer w10: U2.6 5166.5,6020.35 5328.05,5858.8 U3.4@5328.05,5847.45
RADIO_TXEN: U2.7 U4.2 | length 34
  Bottom Layer w10: U2.7@5156.85,5915 5161.85,5910 5181.85,5899.15 5181.85,5895
VCC: D1.2 DC1.1 H2.1 U16.1 | length 2025.1
  Top Layer w78.74: U16.1 4340.43,4068.58 4649.97,4378.11 DC1.1 4755.3,4626.55 4606.48,4775.37 D1.2
  Bottom Layer w59.06: H2.1 4191.85,4840 4668.74,4363.11 4740.3,4363.11 DC1.1
pads on no net: U1.30 U1.37 U1.40 U2.21 U3.1 U7.8 U7.9 U7.11 U7.12 U9.1 U10.5 U11.5 U11.6 U13.5 U13.6 U13.7 U13.8

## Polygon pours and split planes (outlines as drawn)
GND on Top Layer (solid, remove dead copper, pour order 0): 3706.85,7205 6821.85,7205 6931.85,7315 6931.85,3830 6641.85,3540 3906.85,3540 3706.85,3740
GND on Inner2 (solid, remove dead copper): 3826.85,7230 7011.85,7230 7051.85,7270 7051.85,3845 6671.85,3465 3756.85,3465 3596.85,3625 3596.85,7000
+5V on Inner2 (solid, remove dead copper): 6056.85,6741.42 5508.18,6741.42 5416.75,6649.99 5348.74,6649.99 5309.38,6610.62 5309.38,5362.52 5081.85,5135 4616.85,5135 4396.85,4915 4246.85,4915 4246.85,5305 4306.85,5365 5081.85,5365 5191.85,5475 5191.85,6615 5336.85,6760 5481.85,6760 5506.85,6785 5907.45,6785 5946.04,6823.59 6053.26,6823.59 6056.85,6820
GND on Bottom Layer (solid, remove dead copper, pour order 4): 3830.97,7256.9 6945.97,7256.9 7055.97,7366.9 7055.97,3881.9 6765.97,3591.9 4030.97,3591.9 3830.97,3791.9
GND on Inner1 (solid, remove dead copper): 3641.85,7420 3811.85,7250 6901.85,7250 6901.85,3630 6556.85,3285 3966.85,3285 3596.85,3655 3596.85,7375

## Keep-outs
Board Outline Layer:
  region: 5534.84,5664.65 6180.95,5664.65 6180.95,5893.43 5534.84,5893.43
  lines w3.94: 4036.85,3924.29 ccw(c4115.59,3924.29) 4115.59,3845.55 ; 4036.85,6916.42 cw(c4115.59,6916.42) 4115.59,6995.16 ; 6320.08,6995.43 cw(c6320.08,6916.69) 6398.82,6916.69 ; 6320.67,3845 ccw(c6320.67,3923.74) 6399.41,3923.74 ; 4036.85,3845.55 4036.85,6995.16 6399.06,6995.16 6399.06,3845.55 4036.85,3845.55

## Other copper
Bottom Layer:
  region net +5V: 5056.85,5750 5161.85,5750 5196.85,5715 5196.85,5685 5247.88,5633.97 5332.88,5633.97 5361.85,5605 5440.08,5605 5440.08,5498.23 5421.85,5480 5395.36,5480 5315.36,5560 5301.85,5560 5271.85,5590 5061.85,5590 5056.85,5595
  region net +5V: 4281.85,4940 4281.85,5185 4306.85,5210 4421.85,5210 4451.85,5240 4494.8,5240 4494.8,5192.95 4366.85,5065 4366.85,4940

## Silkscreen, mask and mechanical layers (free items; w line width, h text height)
Top Silkscreen Layer:
  text "OLED" at 5461.85,6020 h78.74
  text "-" at 4156.35,5000 h120
  text "JLCJLCJLCJLC" at 6136.85,4770 h78.74 r90
  text "+" at 4156.85,4725 h120
  text "SN:" at 6131.85,4645 h78.74 r90
  text "PD -> DC" at 4576.85,4455 h78.74
  text "ESP32S3-PICO" at 5786.85,4415 h120 r90
  text "12V PD" at 4261.85,3890 h120 r90
  text "7-20V" at 5041.85,3865 h78.74
Bottom Silkscreen Layer:
  text "GY-BMI160" at 5766.85,6690 h78.74 r90
  text "7-20V" at 3196.85,6125 h78.74
  text "E22-XXXMXXS" at 4871.85,5695 h78.74
Top Solder Mask Layer:
  region: 4321.85,6530 4321.85,5520 4946.85,5520 4946.85,6530
  text "T-Meshtatics" at 5151.85,5435 h118.11 r270
  text "CATION HOT" at 4301.85,5320 h118.11
Bottom Solder Mask Layer:
  region: 4326.85,6530 4326.85,5520 4946.85,5520 4946.85,6530
  text "T-Meshtatics" at 6326.85,3975 h181.1
  text "Designed by Tacoin" at 5766.85,3875 h62.99

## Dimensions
4323.85,3535 to 4966.85,3535 on Document Layer
3746.85,3957.64 to 3746.85,4980 on Document Layer
4340.43,3315 to 4970.35,3315 on Document Layer
4323.84,3000 to 4966.85,3000 on Document Layer
4340.43,3666.09 to 4970.35,3666.09 on Document Layer
4031.85,7120 to 6399.06,7120 on Document Layer
6766.85,7005 to 6766.85,3840 on Document Layer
